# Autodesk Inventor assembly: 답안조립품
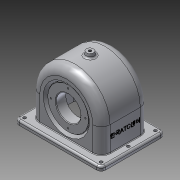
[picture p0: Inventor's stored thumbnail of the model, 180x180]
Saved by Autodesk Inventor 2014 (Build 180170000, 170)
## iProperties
Created: 2015-09
Part Number: 답안조립품
Document SubType Name: Assembly
Designer: Administrator
Author: Administrator
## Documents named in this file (2)
- C:\Users\Administrator\Desktop\450907V1044\답안조립품.iam
- C:\Users\Administrator\Desktop\450907V1044\1-본체.ipt
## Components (1 placed, 1 different names)
1. 1-본체:1
